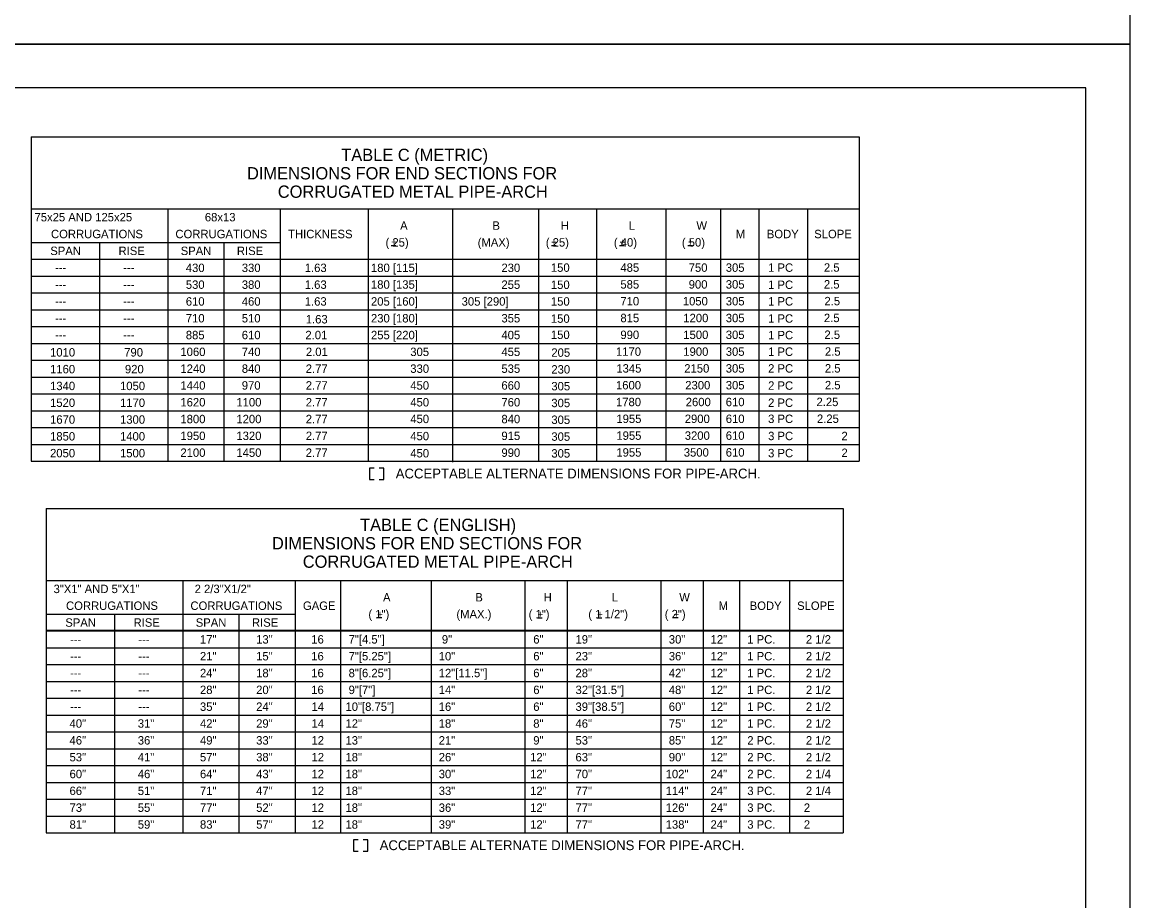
# Model space of a CAD drawing. Extents: x -17 to 888, y -473 to 715.
# Drawn here: x 444.9 to 823.8, y -172.4 to 128.4 of the extents above; entities that cross this region are included whole.
import ezdxf

# ---------------------------------------------------------------- set-up
doc = ezdxf.new("R2010")
doc.units = 0
for name, color, linetype in [('1', 7, 'Continuous'), ('2', 7, 'Continuous'), ('3', 7, 'Continuous'), ('PLT-BNDY', 7, 'Continuous')]:
    doc.layers.add(name, color=color, linetype=linetype)

msp = doc.modelspace()

# ---------------------------------------------------------------- linework, layer by layer
at = {"layer": '1'}
msp.add_lwpolyline([(808.79, -458.11), (808.79, 105.89), (22.79, 105.89), (22.79, -458.11), (808.79, -458.11), (808.79, -431.75), (608.79, -431.75), (608.79, -367.07), (808.79, -367.07), (808.79, -338.11), (608.79, -338.11), (608.79, -458.11), (687.6, -458.11), (687.6, -431.75), (687.6, -458.11), (764.6, -458.11), (764.6, -431.75), (764.6, -444.07), (808.79, -444.07)], dxfattribs=at)
at = {"layer": '2'}
for p, q in [((571.07, 51.94), (572.68, 51.94)), ((625.89, 51.92), (627.49, 51.92)), ((649.17, 51.91), (650.78, 51.91)), ((672.59, 51.94), (674.19, 51.94)), ((566.31, -75.42), (567.91, -75.42)), ((621.13, -75.44), (622.73, -75.44)), ((641.53, -75.45), (643.13, -75.45)), ((667.69, -75.42), (669.29, -75.42))]:
    msp.add_line(p, q, dxfattribs=at)
at = {"layer": '3'}
for p, q in [((447.97, 89.16), (731.23, 89.16)), ((447.97, 89.16), (447.97, -21.87)), ((731.23, 89.16), (731.23, -21.87)), ((447.97, 64.52), (494.65, 64.52)), ((494.65, 64.52), (494.65, -21.87)), ((494.65, 64.52), (533.08, 64.52)), ((533.08, 64.52), (731.23, 64.52)), ((533.08, 64.52), (533.08, -21.87)), ((563.19, 64.52), (563.19, -21.87)), ((621.51, 64.52), (621.51, -21.87)), ((641.35, 64.52), (641.35, -21.87)), ((645.69, 64.52), (676.7, 64.52)), ((665.06, 64.52), (665.06, -21.87)), ((676.7, 64.52), (708.76, 64.52)), ((683.7, 64.52), (683.7, -21.87)), ((696.88, 64.52), (696.88, -21.87)), ((708.76, 64.52), (723.29, 64.52)), ((713.56, 64.52), (713.56, -21.87)), ((592.11, 64.14), (592.11, -22.25)), ((447.97, 53), (533.08, 53)), ((447.97, 53), (471.31, 53)), ((471.31, 53), (471.31, -21.87)), ((471.31, 53), (494.65, 53)), ((494.65, 53), (494.65, 53)), ((494.65, 53), (513.87, 53)), ((513.87, 53), (513.87, -21.87)), ((513.87, 53), (533.08, 53)), ((447.97, 47.24), (731.23, 47.24)), ((447.97, 41.49), (731.23, 41.49)), ((447.97, 35.73), (731.23, 35.73)), ((447.97, 29.97), (731.23, 29.97)), ((447.97, 24.21), (731.23, 24.21)), ((447.97, 18.45), (731.23, 18.45)), ((447.97, 12.69), (731.23, 12.69)), ((447.97, 6.93), (731.23, 6.93)), ((447.97, 1.17), (731.23, 1.17)), ((447.97, -4.59), (731.23, -4.59)), ((447.97, -10.35), (731.23, -10.35)), ((447.97, -16.11), (731.23, -16.11)), ((447.97, -21.87), (447.97, -21.87)), ((447.97, -21.87), (545.07, -21.87)), ((545.07, -21.87), (731.23, -21.87)), ((453.11, -38.07), (453.11, -149.1)), ((453.11, -38.07), (725.74, -38.07)), ((725.74, -38.07), (725.74, -149.1)), ((453.11, -62.7), (725.74, -62.7)), ((453.11, -62.7), (499.8, -62.7)), ((499.8, -62.7), (499.8, -149.1)), ((499.8, -62.7), (538.22, -62.7)), ((538.22, -62.7), (538.22, -149.1)), ((553.73, -62.7), (553.73, -149.1)), ((553.73, -62.7), (584.74, -62.7)), ((584.74, -62.7), (584.74, -149.1)), ((584.74, -62.7), (616.79, -62.7)), ((616.79, -62.7), (616.79, -149.1)), ((616.79, -62.7), (631.32, -62.7)), ((631.32, -62.7), (631.32, -149.1)), ((631.32, -62.7), (663.37, -62.7)), ((663.37, -62.7), (663.37, -149.1)), ((663.37, -62.7), (677.84, -62.7)), ((677.84, -62.7), (677.84, -149.1)), ((690.26, -62.7), (690.26, -149.1)), ((707.32, -62.7), (707.32, -149.1)), ((453.11, -74.22), (538.22, -74.22)), ((453.11, -74.22), (476.45, -74.22)), ((476.45, -74.22), (476.45, -149.1)), ((476.45, -74.22), (499.8, -74.22)), ((499.8, -74.22), (499.8, -74.22)), ((499.8, -74.22), (519.01, -74.22)), ((519.01, -74.22), (519.01, -149.1)), ((519.01, -74.22), (538.22, -74.22)), ((453.11, -79.68), (725.74, -79.68)), ((453.11, -79.98), (725.74, -79.98)), ((453.11, -85.74), (725.74, -85.74)), ((453.11, -91.5), (725.74, -91.5)), ((453.11, -97.26), (725.74, -97.26)), ((453.11, -103.02), (725.74, -103.02)), ((453.11, -108.78), (725.74, -108.78)), ((453.11, -114.54), (725.74, -114.54)), ((453.11, -120.3), (725.74, -120.3)), ((453.11, -126.06), (725.74, -126.06)), ((453.11, -131.82), (725.74, -131.82)), ((453.11, -137.58), (725.74, -137.58)), ((453.11, -143.34), (725.74, -143.34)), ((453.11, -149.1), (725.74, -149.1)), ((453.11, -149.1), (453.11, -149.1))]:
    msp.add_line(p, q, dxfattribs=at)
for points in [[(565.31, -24.25), (563.72, -24.25), (563.72, -28.14), (565.31, -28.14)], [(567.03, -28.14), (568.6, -28.14), (568.6, -24.25), (567.03, -24.25)], [(559.82, -151.47), (558.23, -151.47), (558.23, -155.36), (559.82, -155.36)], [(561.54, -155.36), (563.11, -155.36), (563.11, -151.47), (561.54, -151.47)]]:
    msp.add_lwpolyline(points, dxfattribs=at)
at = {"layer": 'PLT-BNDY'}
for points in [[(-17.21, 714.89), (823.79, 714.89), (823.79, 120.89), (-17.21, 120.89)], [(-17.21, 120.89), (823.79, 120.89), (823.79, -473.11), (-17.21, -473.11)]]:
    msp.add_lwpolyline(points, close=True, dxfattribs=at)

# ---------------------------------------------------------------- texts
at = {"layer": '2'}
for p in [(571.07, 51.91), (625.88, 51.9), (649.17, 51.88), (672.58, 51.91), (566.3, -75.45), (621.12, -75.46), (641.53, -75.48), (667.68, -75.45)]:
    msp.add_text('+', height=2.47, dxfattribs=at).set_placement(p)
at = {"layer": '3'}
for s, height, p in [('TABLE C (METRIC)', 4.2, (554.01, 80.87)), ('DIMENSIONS FOR END SECTIONS FOR', 4.2, (521.78, 74.57)), ('CORRUGATED METAL PIPE-ARCH', 4.2, (532.31, 68.27)), ('75x25 AND 125x25', 2.8799, (449.08, 60.2)), ('68x13', 2.88, (507.35, 60.2)), ('CORRUGATIONS', 2.8799, (454.72, 54.44)), ('CORRUGATIONS', 2.8799, (497.28, 54.44)), ('THICKNESS', 2.88, (535.83, 54.44)), ('A', 2.88, (574.16, 57.32)), ('B', 2.88, (605.74, 57.32)), ('H', 2.88, (629.11, 57.32)), ('L', 2.88, (652.4, 57.32)), ('W', 2.88, (675.51, 57.32)), ('M', 2.88, (688.98, 54.44)), ('BODY', 2.88, (699.6, 54.44)), ('SLOPE', 2.88, (715.82, 54.44)), ('( 25)', 2.88, (569.16, 51.57)), ('(MAX)', 2.88, (600.69, 51.57)), ('( 25)', 2.88, (623.99, 51.57)), ('( 40)', 2.88, (647.28, 51.57)), ('( 50)', 2.88, (670.54, 51.57)), ('SPAN', 2.88, (454.47, 48.68)), ('RISE', 2.88, (477.82, 48.68)), ('SPAN', 2.88, (499.09, 48.68)), ('RISE', 2.88, (518.31, 48.68)), ('430 ', 2.88, (500.84, 42.86)), ('330 ', 2.88, (519.99, 42.86)), ('1.63', 2.88, (541.53, 42.86)), ('180 [115]', 2.88, (564.18, 42.86)), ('230      ', 2.88, (608.81, 42.86)), ('150 ', 2.88, (625.73, 42.94)), ('485 ', 2.88, (649.51, 42.94)), ('750 ', 2.88, (672.88, 42.94)), ('305 ', 2.88, (685.56, 42.94)), ('1 PC', 2.88, (700.04, 42.94)), ('2.5  ', 2.88, (719.14, 42.97)), ('---', 2.88, (456.09, 42.93)), ('---', 2.88, (479.43, 42.93)), ('---', 2.88, (456.09, 37.17)), ('---', 2.88, (479.43, 37.17)), ('530 ', 2.88, (500.84, 37.11)), ('380 ', 2.88, (519.99, 37.11)), ('1.63', 2.88, (541.53, 37.11)), ('180 [135]', 2.88, (564.18, 37.15)), ('255      ', 2.88, (608.81, 37.11)), ('150 ', 2.88, (625.73, 37.07)), ('585 ', 2.88, (649.51, 37.19)), ('900 ', 2.88, (672.88, 37.19)), ('305 ', 2.88, (685.56, 37.19)), ('1 PC', 2.88, (700.04, 37.07)), ('2.5  ', 2.88, (719.14, 37.22)), ('610 ', 2.88, (500.84, 31.36)), ('460 ', 2.88, (519.99, 31.36)), ('1.63', 2.88, (541.53, 31.36)), ('205 [160]', 2.88, (564.18, 31.36)), ('305 [290]', 2.88, (595.2, 31.36)), ('150 ', 2.88, (625.73, 31.36)), ('710 ', 2.88, (649.51, 31.44)), ('1050', 2.88, (670.86, 31.44)), ('305 ', 2.88, (685.56, 31.44)), ('1 PC', 2.88, (700.04, 31.39)), ('2.5  ', 2.88, (719.31, 31.47)), ('---', 2.88, (456.09, 31.41)), ('---', 2.88, (479.43, 31.41)), ('---', 2.88, (456.09, 25.65)), ('---', 2.88, (479.43, 25.65)), ('710 ', 2.88, (500.84, 25.61)), ('510 ', 2.88, (519.99, 25.61)), ('1.63', 2.88, (541.87, 25.27)), ('230 [180]', 2.88, (564.18, 25.61)), ('355      ', 2.88, (608.81, 25.61)), ('150 ', 2.88, (625.73, 25.49)), ('815 ', 2.88, (649.51, 25.69)), ('1200', 2.88, (671.03, 25.69)), ('305 ', 2.88, (685.56, 25.69)), ('1 PC', 2.88, (700.04, 25.52)), ('2.5  ', 2.88, (719.14, 25.72)), ('885 ', 2.88, (500.84, 19.86)), ('610 ', 2.88, (519.99, 19.86)), ('2.01', 2.88, (541.75, 19.86)), ('255 [220]', 2.88, (564.18, 19.86)), ('405      ', 2.88, (608.81, 19.86)), ('150 ', 2.88, (625.73, 19.95)), ('990 ', 2.88, (649.51, 19.94)), ('1500', 2.88, (671.03, 19.94)), ('305 ', 2.88, (685.56, 19.94)), ('1 PC', 2.88, (700.04, 19.84)), ('2.5  ', 2.88, (719.31, 19.97)), ('---', 2.88, (456.09, 19.89)), ('---', 2.88, (479.43, 19.89)), ('1010', 2.88, (454.4, 13.94)), ('790 ', 2.88, (479.76, 13.94)), ('1060', 2.88, (498.99, 14.11)), ('740 ', 2.88, (519.99, 14.11)), ('2.01', 2.88, (541.92, 14.11)), ('305      ', 2.88, (577.63, 14.11)), ('455      ', 2.88, (608.81, 14.11)), ('205 ', 2.88, (625.89, 13.86)), ('1170', 2.88, (648, 14.19)), ('1900', 2.88, (671.03, 14.19)), ('305 ', 2.88, (685.56, 14.19)), ('1 PC', 2.88, (700.04, 14.16)), ('2.5  ', 2.88, (719.48, 14.22)), ('2.5  ', 2.88, (719.48, 8.47)), ('1160', 2.88, (454.4, 8.19)), ('920 ', 2.88, (480.01, 8.19)), ('1240', 2.88, (498.99, 8.36)), ('840 ', 2.88, (519.99, 8.36)), ('2.77', 2.88, (541.87, 8.36)), ('330      ', 2.88, (577.63, 8.36)), ('535      ', 2.88, (608.81, 8.36)), ('230 ', 2.88, (625.89, 8.11)), ('1345', 2.88, (648.13, 8.44)), ('2150', 2.88, (671.36, 8.44)), ('305 ', 2.88, (685.56, 8.44)), ('2 PC', 2.88, (700.04, 8.44)), ('1340', 2.88, (454.4, 2.44)), ('1050', 2.88, (478.33, 2.44)), ('1440', 2.88, (498.99, 2.61)), ('970 ', 2.88, (519.99, 2.61)), ('2.77', 2.88, (541.87, 2.61)), ('450      ', 2.88, (577.63, 2.61)), ('660      ', 2.88, (608.81, 2.61)), ('305 ', 2.88, (625.89, 2.36)), ('1600', 2.88, (648, 2.69)), ('2300', 2.88, (671.7, 2.69)), ('305 ', 2.88, (685.56, 2.69)), ('2 PC', 2.88, (700.04, 2.57)), ('2.5  ', 2.88, (719.48, 2.72)), ('1520', 2.88, (454.4, -3.31)), ('1170', 2.88, (478.33, -3.31)), ('1620', 2.88, (498.99, -3.14)), ('1100', 2.88, (518.14, -3.14)), ('2.77', 2.88, (541.87, -3.14)), ('450      ', 2.88, (577.63, -3.14)), ('760      ', 2.88, (608.81, -3.14)), ('305 ', 2.88, (625.89, -3.39)), ('1780', 2.88, (648, -3.06)), ('2600', 2.88, (671.87, -3.06)), ('610 ', 2.88, (685.56, -3.06)), ('2 PC', 2.88, (700.04, -3.3)), ('2.25 ', 2.88, (716.59, -3.03)), ('1670', 2.88, (454.4, -9.06)), ('1300', 2.88, (478.33, -9.06)), ('1800', 2.88, (498.99, -8.89)), ('1200', 2.88, (518.14, -8.89)), ('2.77', 2.88, (541.87, -8.89)), ('450      ', 2.88, (577.63, -8.85)), ('840      ', 2.88, (608.81, -8.89)), ('305 ', 2.88, (625.89, -9.14)), ('1955', 2.88, (648.13, -8.81)), ('2900', 2.88, (671.53, -8.81)), ('610 ', 2.88, (685.56, -8.81)), ('3 PC', 2.88, (700.04, -8.81)), ('2.25 ', 2.88, (716.75, -8.78)), ('1850', 2.88, (454.4, -14.81)), ('1400', 2.88, (478.33, -14.81)), ('1950', 2.88, (498.99, -14.64)), ('1320', 2.88, (518.14, -14.64)), ('2.77', 2.88, (541.87, -14.64)), ('450      ', 2.88, (577.63, -14.72)), ('915      ', 2.88, (608.81, -14.64)), ('305 ', 2.88, (625.89, -14.89)), ('1955', 2.88, (648.13, -14.56)), ('3200', 2.88, (671.53, -14.56)), ('610 ', 2.88, (685.56, -14.56)), ('3 PC', 2.88, (700.04, -14.68)), ('2    ', 2.88, (725.14, -14.69)), ('2050', 2.88, (454.4, -20.56)), ('1500', 2.88, (478.33, -20.56)), ('2100', 2.88, (498.99, -20.39)), ('1450', 2.88, (518.14, -20.39)), ('2.77', 2.88, (541.87, -20.39)), ('450      ', 2.88, (577.63, -20.59)), ('990      ', 2.88, (608.81, -20.39)), ('305 ', 2.88, (625.89, -20.64)), ('1955', 2.88, (648.13, -20.31)), ('3500', 2.88, (671.2, -20.31)), ('610 ', 2.88, (685.56, -20.31)), ('3 PC', 2.88, (700.04, -20.55)), ('2    ', 2.88, (725.14, -20.44)), ('ACCEPTABLE ALTERNATE DIMENSIONS FOR PIPE-ARCH.', 3.36, (572.65, -27.78)), ('TABLE C (ENGLISH)', 4.2, (560.46, -45.76)), ('DIMENSIONS FOR END SECTIONS FOR', 4.2, (530.31, -52.06)), ('CORRUGATED METAL PIPE-ARCH', 4.2, (540.85, -58.36)), ('3"X1" AND 5"X1"', 2.8797, (455.59, -67.02)), ('2 2/3"X1/2"', 2.8797, (503.86, -67.02)), ('A', 2.88, (568.3, -69.9)), ('B', 2.88, (599.88, -69.9)), ('H', 2.88, (623.25, -69.9)), ('L', 2.88, (646.54, -69.9)), ('W', 2.88, (669.65, -69.9)), ('CORRUGATIONS', 2.88, (459.86, -72.78)), ('CORRUGATIONS', 2.88, (502.42, -72.78)), ('GAGE', 2.88, (540.91, -72.78)), ('M', 2.88, (683.12, -72.78)), ('BODY', 2.88, (693.74, -72.78)), ('SLOPE', 2.88, (709.96, -72.78)), ('SPAN', 2.88, (459.61, -78.54)), ('RISE', 2.88, (482.97, -78.54)), ('SPAN', 2.88, (504.23, -78.54)), ('RISE', 2.88, (523.46, -78.54)), ('( 1")', 2.88, (563.3, -75.66)), ('(MAX.)', 2.88, (593.41, -75.66)), ('( 1")', 2.88, (618.13, -75.66)), ('( 1 1/2")', 2.88, (638.54, -75.66)), ('( 2")', 2.88, (664.68, -75.66)), ('---', 2.88, (461.23, -84.3)), ('---', 2.88, (484.58, -84.3)), ('17"', 2.88, (505.68, -84.3)), ('13"', 2.88, (524.9, -84.3)), ('16', 2.88, (543.75, -84.3)), (' 7"[4.5"]', 2.88, (555.46, -84.3)), (' 9"', 2.88, (587.36, -84.3)), (' 6"', 2.88, (618.63, -84.3)), ('19"', 2.88, (634.15, -84.3)), (' 30"', 2.88, (665, -84.3)), ('12"', 2.88, (680.35, -84.3)), ('1 PC.', 2.88, (692.92, -84.3)), ('2 1/2', 2.88, (712.97, -84.3)), ('21"', 2.88, (505.68, -90.06)), ('16', 2.88, (543.75, -90.06)), (' 7"[5.25"]', 2.88, (555.46, -90.06)), ('10"', 2.88, (587.36, -90.06)), (' 6"', 2.88, (618.63, -90.06)), ('23"', 2.88, (634.15, -90.06)), (' 36"', 2.88, (665, -90.06)), ('12"', 2.88, (680.35, -90.06)), ('1 PC.', 2.88, (692.92, -90.06)), ('2 1/2', 2.88, (712.97, -90.06)), ('---', 2.88, (461.23, -90.06)), ('---', 2.88, (484.58, -90.06)), ('15"', 2.88, (524.9, -90.06)), ('---', 2.88, (461.23, -95.82)), ('---', 2.88, (484.58, -95.82)), ('24"', 2.88, (505.68, -95.82)), ('18"', 2.88, (524.9, -95.82)), ('16', 2.88, (543.75, -95.82)), (' 8"[6.25"]', 2.88, (555.46, -95.82)), ('12"[11.5"]', 2.88, (587.36, -95.82)), (' 6"', 2.88, (618.63, -95.82)), ('28"', 2.88, (634.15, -95.82)), (' 42"', 2.88, (665, -95.82)), ('12"', 2.88, (680.35, -95.82)), ('1 PC.', 2.88, (692.92, -95.82)), ('2 1/2', 2.88, (712.97, -95.82)), ('---', 2.88, (461.23, -101.58)), ('---', 2.88, (484.58, -101.58)), ('28"', 2.88, (505.68, -101.58)), ('20"', 2.88, (524.9, -101.58)), ('16', 2.88, (543.75, -101.58)), (' 9"[7"]', 2.88, (555.46, -101.58)), ('14"', 2.88, (587.36, -101.58)), (' 6"', 2.88, (618.63, -101.58)), ('32"[31.5"]', 2.88, (634.15, -101.58)), (' 48"', 2.88, (665, -101.58)), ('12"', 2.88, (680.35, -101.58)), ('1 PC.', 2.88, (692.92, -101.58)), ('2 1/2', 2.88, (712.97, -101.58)), ('---', 2.88, (461.23, -107.34)), ('---', 2.88, (484.58, -107.34)), ('35"', 2.88, (505.68, -107.34)), ('24"', 2.88, (524.9, -107.34)), ('14', 2.88, (543.83, -107.34)), ('10"[8.75"]', 2.88, (555.46, -107.34)), ('16"', 2.88, (587.36, -107.34)), (' 6"', 2.88, (618.63, -107.34)), ('39"[38.5"]', 2.88, (634.15, -107.34)), (' 60"', 2.88, (665, -107.34)), ('12"', 2.88, (680.35, -107.34)), ('1 PC.', 2.88, (692.92, -107.34)), ('2 1/2', 2.88, (712.97, -107.34)), ('40"', 2.88, (461.06, -113.1)), ('31"', 2.88, (484.41, -113.1)), ('42"', 2.88, (505.68, -113.1)), ('29"', 2.88, (524.9, -113.1)), ('14', 2.88, (543.83, -113.1)), ('12"', 2.88, (555.46, -113.1)), ('18"', 2.88, (587.36, -113.1)), (' 8"', 2.88, (618.63, -113.1)), ('46"', 2.88, (634.15, -113.1)), (' 75"', 2.88, (665, -113.1)), ('12"', 2.88, (680.35, -113.1)), ('1 PC.', 2.88, (692.92, -113.1)), ('2 1/2', 2.88, (712.97, -113.1)), ('46"', 2.88, (461.06, -118.86)), ('36"', 2.88, (484.41, -118.86)), ('49"', 2.88, (505.68, -118.86)), ('33"', 2.88, (524.9, -118.86)), ('12', 2.88, (543.83, -118.86)), ('13"', 2.88, (555.46, -118.86)), ('21"', 2.88, (587.36, -118.86)), (' 9"', 2.88, (618.63, -118.86)), ('53"', 2.88, (634.15, -118.86)), (' 85"', 2.88, (665, -118.86)), ('12"', 2.88, (680.35, -118.86)), ('2 PC.', 2.88, (692.92, -118.86)), ('2 1/2', 2.88, (712.97, -118.86)), ('53"', 2.88, (461.06, -124.62)), ('41"', 2.88, (484.41, -124.62)), ('57"', 2.88, (505.68, -124.62)), ('38"', 2.88, (524.9, -124.62)), ('12', 2.88, (543.83, -124.62)), ('18"', 2.88, (555.46, -124.62)), ('26"', 2.88, (587.36, -124.62)), ('12"', 2.88, (618.63, -124.62)), ('63"', 2.88, (634.15, -124.62)), (' 90"', 2.88, (665, -124.62)), ('12"', 2.88, (680.35, -124.62)), ('2 PC.', 2.88, (692.92, -124.62)), ('2 1/2', 2.88, (712.97, -124.62)), ('60"', 2.88, (461.06, -130.38)), ('46"', 2.88, (484.41, -130.38)), ('64"', 2.88, (505.68, -130.38)), ('43"', 2.88, (524.9, -130.38)), ('12', 2.88, (543.83, -130.38)), ('18"', 2.88, (555.46, -130.38)), ('30"', 2.88, (587.36, -130.38)), ('12"', 2.88, (618.63, -130.38)), ('70"', 2.88, (634.15, -130.38)), ('102"', 2.88, (665, -130.38)), ('24"', 2.88, (680.35, -130.38)), ('2 PC.', 2.88, (692.92, -130.38)), ('2 1/4', 2.88, (712.97, -130.38)), ('66"', 2.88, (461.06, -136.14)), ('51"', 2.88, (484.41, -136.14)), ('71"', 2.88, (505.68, -136.14)), ('47"', 2.88, (524.9, -136.14)), ('12', 2.88, (543.83, -136.14)), ('18"', 2.88, (555.46, -136.14)), ('33"', 2.88, (587.36, -136.14)), ('12"', 2.88, (618.63, -136.14)), ('77"', 2.88, (634.15, -136.14)), ('114"', 2.88, (665, -136.14)), ('24"', 2.88, (680.35, -136.14)), ('3 PC.', 2.88, (692.92, -136.14)), ('2 1/4', 2.88, (712.97, -136.14)), ('73"', 2.88, (461.06, -141.9)), ('55"', 2.88, (484.41, -141.9)), ('77"', 2.88, (505.68, -141.9)), ('52"', 2.88, (524.9, -141.9)), ('12', 2.88, (543.83, -141.9)), ('18"', 2.88, (555.46, -141.9)), ('36"', 2.88, (587.36, -141.9)), ('12"', 2.88, (618.63, -141.9)), ('77"', 2.88, (634.15, -141.9)), ('126"', 2.88, (665, -141.9)), ('24"', 2.88, (680.35, -141.9)), ('3 PC.', 2.88, (692.92, -141.9)), ('2  ', 2.88, (712.26, -141.9)), ('81"', 2.88, (461.06, -147.66)), ('59"', 2.88, (484.41, -147.66)), ('83"', 2.88, (505.68, -147.66)), ('57"', 2.88, (524.9, -147.66)), ('12', 2.88, (543.83, -147.66)), ('18"', 2.88, (555.46, -147.66)), ('39"', 2.88, (587.36, -147.66)), ('12"', 2.88, (618.63, -147.66)), ('77"', 2.88, (634.15, -147.66)), ('138"', 2.88, (665, -147.66)), ('24"', 2.88, (680.35, -147.66)), ('3 PC.', 2.88, (692.92, -147.66)), ('2  ', 2.88, (712.26, -147.66)), ('ACCEPTABLE ALTERNATE DIMENSIONS FOR PIPE-ARCH.', 3.36, (567.16, -155))]:
    msp.add_text(s, height=height, dxfattribs=at).set_placement(p)

doc.saveas('drawing.dxf')
